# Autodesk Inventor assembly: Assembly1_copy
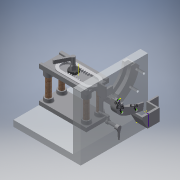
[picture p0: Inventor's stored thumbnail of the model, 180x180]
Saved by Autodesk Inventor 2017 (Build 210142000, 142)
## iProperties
Created: 2017-04
Part Number: Assembly1_copy
Document SubType Name: Assembly
Designer: 1460374
Author: 1460374
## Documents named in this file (19)
- R:\STEM 1st Pd\JacobPatCandy\Assembly1_copy.iam
- R:\STEM 1st Pd\JacobPatCandy\BasePlate.ipt
- R:\STEM 1st Pd\JacobPatCandy\RampV2.ipt
- R:\STEM 1st Pd\JacobPatCandy\RampPlate.ipt
- R:\STEM 1st Pd\JacobPatCandy\platform.ipt
- R:\STEM 1st Pd\JacobPatCandy\guard.ipt
- R:\STEM 1st Pd\JacobPatCandy\Connector.ipt
- R:\STEM 1st Pd\JacobPatCandy\Gearv2.ipt
- R:\STEM 1st Pd\JacobPatCandy\handle.ipt
- R:\STEM 1st Pd\JacobPatCandy\platform2.ipt
- R:\STEM 1st Pd\JacobPatCandy\platform2_2.ipt
- R:\STEM 1st Pd\JacobPatCandy\push.ipt
- R:\STEM 1st Pd\JacobPatCandy\SwirlPiece.ipt
- R:\STEM 1st Pd\JacobPatCandy\SwirlPath.ipt
- R:\STEM 1st Pd\JacobPatCandy\SwirlPathWall.ipt
- R:\STEM 1st Pd\JacobPatCandy\Bowl.ipt
- R:\STEM 1st Pd\JacobPatCandy\partial_gear.ipt
- R:\STEM 1st Pd\JacobPatCandy\gear handle.ipt
- R:\STEM 1st Pd\JacobPatCandy\pillar.ipt
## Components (18 placed, 18 different names)
1. BasePlate:1 — Mate:8, Mate:9, Mate:10, Mate:11, Mate:12, Mate:23, Mate:28, Mate:31, Mate:32, Mate:35, Flush:5, Flush:6, Flush:7, Flush:8, Flush:9, Flush:10, Flush:14, Flush:15, Flush:16, Mate:47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
2. RampV2:1 — Mate:5, Mate:6, Mate:7, Mate:8, Mate:9, Flush:1, Mate:49
3. RampPlate:1 — Mate:5, Mate:6, Mate:7
4. platform:1 — Mate:47, Mate:48, Mate:49
5. guard:1 — Flush:1, Mate:10, Mate:11, Mate:12
6. Connector:1 — Mate:30, Mate:48, Mate:50
7. Gearv2:1 — Mate:23, Mate:25, Mate:26, Mate:28, Mate:30, Mate:32, Mate:50
8. handle:1 — Mate:25, Mate:26, Mate:31
9. platform2:1 — Flush:18, Flush:21
10. platform2_2:1 — Mate:44, Mate:46, Flush:20, Mate:52, Mate:53, Mate:54, Mate:55
11. push:1 — Mate:35, Mate:44, Flush:20
12. SwirlPiece:1 — Flush:5
13. SwirlPath:1 — Flush:6, Flush:7, Flush:8, Flush:9, Flush:10, Flush:12, Flush:13
14. SwirlPathWall:1 — Flush:12, Flush:13
15. Bowl:1 — Flush:14, Flush:15, Flush:16
16. partial_gear:1 — Mate:41, Mate:42, Mate:43, Mate:46, Mate:55
17. gear handle:1 — Mate:41, Mate:42, Mate:43
18. pillar:1 — Flush:19, Mate:52, Mate:53, Mate:54
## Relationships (45: Mate 29, Flush 16)
- Mate:5: RampV2:1 ↔ RampPlate:1
- Mate:6: RampV2:1 ↔ RampPlate:1
- Mate:7: RampV2:1 ↔ RampPlate:1
- Mate:8: BasePlate:1 ↔ RampV2:1
- Mate:9: BasePlate:1 ↔ RampV2:1
- Flush:1: RampV2:1 ↔ guard:1
- Mate:10: BasePlate:1 ↔ guard:1
- Mate:11: BasePlate:1 ↔ guard:1
- Mate:12: BasePlate:1 ↔ guard:1
- Mate:23: BasePlate:1 ↔ Gearv2:1
- Mate:25: Gearv2:1 ↔ handle:1
- Mate:26: Gearv2:1 ↔ handle:1
- Mate:28: BasePlate:1 ↔ Gearv2:1
- Mate:30: Connector:1 ↔ Gearv2:1
- Mate:31: BasePlate:1 ↔ handle:1
- Mate:32: BasePlate:1 ↔ Gearv2:1
- Mate:35: BasePlate:1 ↔ push:1
- Flush:5: BasePlate:1 ↔ SwirlPiece:1
- Flush:6: BasePlate:1 ↔ SwirlPath:1
- Flush:7: BasePlate:1 ↔ SwirlPath:1
- Flush:8: BasePlate:1 ↔ SwirlPath:1
- Flush:9: BasePlate:1 ↔ SwirlPath:1
- Flush:10: BasePlate:1 ↔ SwirlPath:1
- Flush:12: SwirlPath:1 ↔ SwirlPathWall:1
- Flush:13: SwirlPath:1 ↔ SwirlPathWall:1
- Flush:14: BasePlate:1 ↔ Bowl:1
- Flush:15: BasePlate:1 ↔ Bowl:1
- Flush:16: BasePlate:1 ↔ Bowl:1
- Mate:41: partial_gear:1 ↔ gear handle:1
- Mate:42: partial_gear:1 ↔ gear handle:1
- Mate:43: partial_gear:1 ↔ gear handle:1
- Mate:44: platform2_2:1 ↔ push:1
- Mate:46: platform2_2:1 ↔ partial_gear:1
- Mate:47: BasePlate:1 ↔ platform:1
- Mate:48: platform:1 ↔ Connector:1
- Mate:49: RampV2:1 ↔ platform:1
- Flush:18: BasePlate:1 ↔ platform2:1
- Flush:19: BasePlate:1 ↔ pillar:1
- Mate:50: Connector:1 ↔ Gearv2:1
- Flush:20: platform2_2:1 ↔ push:1
- Mate:52: platform2_2:1 ↔ pillar:1
- Mate:53: platform2_2:1 ↔ pillar:1
- Mate:54: platform2_2:1 ↔ pillar:1
- Flush:21: BasePlate:1 ↔ platform2:1
- Mate:55: platform2_2:1 ↔ partial_gear:1
